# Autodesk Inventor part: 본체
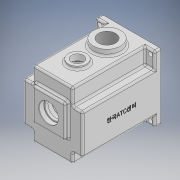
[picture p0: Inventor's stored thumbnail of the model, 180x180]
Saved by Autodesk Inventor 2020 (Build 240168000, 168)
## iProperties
Created: 2022-01
Part Number: 본체
Material: 일반
Document SubType Name: Modeling
Designer: user
Density: 1 g/cm^3
Appearance: 기본값
Mass: 521.293 g
Surface Area: 1157.23 cm^2
Volume: 521.293 cm^3
Author: user
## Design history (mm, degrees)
sketch "스케치1"
  geometry: L1 (49, -55)-(-49, -55); L2 (-49, -55)-(-49, 55); L3 (-49, 55)-(49, 55); L4 (49, 55)-(49, -55); L5 (49, -55)-(-49, 55); L6 (-49, -55)-(49, 55); 1 further point
  constraints: 12 end point, 2 midpoint, 2 parallel, 1 horizontal, 1 perpendicular
  dimensions: "d0" = 98 distance of L2.end L3.end; "d1" = 110 distance of L1.end L2.end
extrude "돌출1" new body sketch "스케치1" distance "d2" = 130; taper "d3" = 0 deg
sketch "스케치2"
  geometry: L1 (-49, 55)-(-49, -55) reference; L2 (-49, -55)-(-33, -55); L3 (-33, -55)-(-33, -38); L4 (-33, -38)-(-49, -38); L5 (-49, -38)-(-49, -55); L6 (49, 55)-(-49, 55) reference; L7 (-49, 55)-(-33, 55); L8 (-33, 55)-(-33, 28); L9 (-33, 28)-(-49, 28); L10 (-49, 28)-(-49, 55); L11 (0, 55)-(0, -55); L12 (-49, -55)-(49, -55) reference; L13 (49, 55)-(33, 55); L14 (33, 55)-(33, 28); L15 (33, 28)-(49, 28); L16 (49, 28)-(49, 55); L17 (49, -55)-(33, -55); L18 (33, -55)-(33, -38); L19 (33, -38)-(49, -38); L20 (49, -38)-(49, -55); 5 further points
  constraints: 34 end point, 6 symmetric about line, 4 parallel, 2 horizontal, 2 midpoint, 2 perpendicular
  dimensions: "d4" = 16 distance of L3.end L4.end; "d5" = 17 distance of L2.end L3.end; "d6" = 16 distance of L8.end L9.end; "d7" = 27 distance of L7.end L8.end
extrude "돌출2" cut sketch "스케치2" distance "d8" = 120; taper "d9" = 0 deg
sketch "스케치3"
  geometry: L1 (49, 0)-(49, -130); L2 (82, -130)-(16, -130) reference; L3 (98, 0)-(0, 0) reference; C1 r 15 at (49, -89); C2 r 22.5 at (49, -40)
  constraints: 2 centre point, 2 end point, 2 point on line, 1 midpoint
  dimensions: "d10" = 30 diameter of C1; "d11" = 45 diameter of C2; "d12" = 40 distance from line of L3 C2.centre; "d13" = 49 distance of C1.centre C2.centre
extrude "돌출3" join sketch "스케치3" distance "d14" = 10; taper "d15" = 0 deg
sketch "스케치4"
  geometry: L1 (22.5, 65)-(-22.5, 65) reference; L2 (0, 65)-(0, -55); L3 (33, -55)-(-33, -55) reference; L4 (49, -55)-(-49, -55) reference; L5 (23, -1)-(-23, -1); L6 (-23, -1)-(-23, 30.143); L7 (-23, 45)-(23, 45); L8 (23, 45)-(23, 30.143); L9 (23, -1)-(-23, 45); L10 (-23, -1)-(23, 45); L11 (-23, 30.143)-(-23, 45); L12 (23, 30.143)-(23, -1); A1 r 42 centre (0, -5) between (23, 30.143) and (-23, 30.143); A2 r 42 centre (0, -5) between (0, -47) and (23, 30.143); A3 r 42 centre (0, -5) between (-23, 30.143) and (0, -47); 2 further points
  constraints: 18 end point, 6 point on circle, 5 parallel, 4 midpoint, 3 centre point, 3 point on line, 2 perpendicular, 1 horizontal
  dimensions: "d35" = 84 diameter of A1; "d36" = 50 distance from line of L4 A1.centre; "d37" = 46 distance of L7.start L7.end; "d38" = 46 distance of L5.end L7.start; "d39" = 50 distance from line of A1.centre L7
extrude "돌출4" cut sketch "스케치4" distance "d20" = 121; taper "d21" = 0 deg
sketch "스케치7"
  geometry: L1 (33, 55)-(-33, 55) reference; L2 (0, 55)-(0, -55); L3 (-33, -55)-(33, -55) reference; L4 (27, -21)-(-27, -21); L5 (-27, -21)-(-27, 33); L6 (-27, 33)-(27, 33); L7 (27, 33)-(27, -21); L8 (27, -21)-(-27, 33); L9 (-27, -21)-(27, 33); A1 r 42 centre (0, -5) between (-23, 30.143) and (23, 30.143) reference; 2 further points
  constraints: 14 end point, 4 midpoint, 2 parallel, 1 horizontal, 1 perpendicular, 1 point on line
  dimensions: "d40" = 54 distance of L5.end L6.end; "d41" = 54 distance of L4.end L5.end; "d42" = 11 distance of point (0, 6) A1.centre
extrude "돌출7" join sketch "스케치7" distance "d43" = 7; taper "d44" = 0 deg
fillet "모깎기3" dims "d45" = 6
fillet "모깎기4" dims "d46" = 3
sketch "스케치8"
  geometry: L1 (23, 42)-(23, 33.249) reference; L2 (-20, 45)-(20, 45) reference; L3 (-23, 33.249)-(-23, 42) reference; L4 (-26, 33.249)-(-26, 42); L5 (-20, 48)-(20, 48); L6 (26, 42)-(26, 33.249); A1 r 42 centre (0, -5) between (-25.375, 28.468) and (25.375, 28.468) reference; A2 r 6 centre (29, 33.249) between (23, 33.249) and (25.375, 28.468) reference; A3 r 3 centre (20, 42) between (23, 42) and (20, 45) reference; A4 r 3 centre (-20, 42) between (-20, 45) and (-23, 42) reference; A5 r 6 centre (-29, 33.249) between (-25.375, 28.468) and (-23, 33.249) reference; A6 r 45 centre (0, -5) between (-27.188, 30.859) and (27.187, 30.859); A7 r 3 centre (-29, 33.249) between (-27.188, 30.859) and (-26, 33.249); A8 r 6 centre (-20, 42) between (-20, 48) and (-26, 42); A9 r 6 centre (20, 42) between (26, 42) and (20, 48); A10 r 3 centre (29, 33.249) between (26, 33.249) and (27.187, 30.859); 1 further point
  constraints: 10 point on circle, 6 end point, 5 centre point, 7 other
  dimensions: "d47" = 3 radial gap between concentric circles of A1 A6
extrude "돌출8" cut sketch "스케치8" distance "d48" = 9; taper "d49" = 0 deg
chamfer "모따기2" distance "d50" = 1; stored, may be unused: second distance "d51" = 2, angle "d52" = 45 deg
sketch "스케치9"
  geometry: C1 r 15 at (20, -32) reference; C2 r 22.5 at (20, -81) reference; C3 r 15 at (20, -32); 1 further point
  constraints: 1 centre point, 1 coincident
  dimensions: "d53" = 30 diameter of C3
extrude "돌출9" cut sketch "스케치9" distance "d54" = 5; taper "d55" = 0 deg
sketch "스케치10"
  geometry: C1 r 15 at (0, 0) reference; 2 further points
  constraints: 1 coincident
hole "구멍1" sketch "스케치10" at (0, 0) diameter "d56" = 20; stored, may be unused: countersink angle "d60" = 90 deg, drill point angle "d62" = 0 deg; dims "d57" = 4, "d58" = 4, "d59" = 2, "d61" = 6
chamfer "모따기3" distance "d63" = 1; stored, may be unused: second distance "d64" = 2, angle "d65" = 45 deg
sketch "스케치11"
  geometry: C1 r 22.5 at (0, 0) reference; 2 further points
  constraints: 1 coincident
hole "구멍2" sketch "스케치11" at (0, 0) diameter "d66" = 28.376; stored, may be unused: countersink angle "d70" = 90 deg, drill point angle "d72" = 0 deg; dims "d67" = 60, "d68" = 4, "d69" = 2, "d71" = 67.3
sketch "스케치12"
  geometry: L1 (27, 33)-(-27, 33) reference; L2 (27, -21)-(27, 33) reference; L3 (-27, 33)-(27, 33) reference; L4 (0, 33)-(0, -21); L5 (-27, 33)-(-27, -21) reference; L6 (-27, -21)-(27, -21) reference; L7 (-27, -21)-(-27, 33) reference; L8 (-27, 6)-(27, 6); L9 (27, 33)-(27, -21) reference; C1 r 16 at (0, 6); A1 r 42 centre (0, -5) between (-25.375, 28.468) and (25.375, 28.468) reference; 1 further point
  constraints: 4 end point, 4 midpoint, 1 centre point, 1 vertical
  dimensions: "d73" = 32 diameter of C1
extrude "돌출10" cut sketch "스케치12" distance "d74" = 8.3; taper "d75" = 0 deg
sketch "스케치13"
  geometry: C1 r 16 at (0, 6) reference; C2 r 21 at (0, 6); 1 further point
  constraints: 1 centre point, 1 coincident
  dimensions: "d76" = 42 diameter of C2
extrude "돌출11" join sketch "스케치13" distance "d77" = 7; taper "d78" = 0 deg
sketch "스케치14"
  geometry: C1 r 21 at (0, 0) reference; C2 r 17.5 at (0, 0); 1 further point
  constraints: 1 centre point, 1 coincident
  dimensions: "d79" = 35 diameter of C2
extrude "돌출12" cut sketch "스케치14" distance "d80" = 10; taper "d81" = 0 deg
sketch "스케치15"
  geometry: C1 r 16 at (0, 0) reference; C2 r 14 at (0, 0); 1 further point
  constraints: 1 centre point, 1 coincident
  dimensions: "d82" = 28 diameter of C2
extrude "돌출13" cut sketch "스케치15" stored distance "d83" = 10; taper "d84" = 0 deg
sketch "스케치16"
  geometry: L1 (33, -55)-(-33, -55) reference; L2 (0, -55)-(0, 55); L3 (-33, 55)-(33, 55) reference; C1 r 15 at (0, -25); 1 further point
  constraints: 2 end point, 2 midpoint, 1 centre point, 1 point on line
  dimensions: "d85" = 30 diameter of C1; "d86" = 30 distance from line of L1 C1.centre
extrude "돌출14" join sketch "스케치16" distance "d87" = 7; taper "d88" = 0 deg
sketch "스케치17"
  geometry: C1 r 11 at (0, -25); A1 r 15 centre (0, -25) between (-8.978, -12.984) and (8.978, -12.984) reference; 1 further point
  constraints: 1 centre point, 1 coincident
  dimensions: "d89" = 22 diameter of C1
extrude "돌출15" cut sketch "스케치17" distance "d90" = 7; taper "d91" = 0 deg
sketch "스케치18"
  geometry: C1 r 11 at (0, 0) reference; C2 r 9.5 at (0, 0); 1 further point
  constraints: 1 centre point, 1 coincident
  dimensions: "d92" = 19 diameter of C2
extrude "돌출16" cut sketch "스케치18" distance "d93" = 3; taper "d94" = 0 deg
fillet "모깎기5" dims "d95" = 3
fillet "모깎기6" dims "d96" = 0.3
chamfer "모따기4" distance "d97" = 1; stored, may be unused: second distance "d98" = 2, angle "d99" = 45 deg
chamfer "모따기5" distance "d100" = 0.8; stored, may be unused: second distance "d101" = 2, angle "d102" = 30 deg
fillet "모깎기7" dims "d103" = 0.3
fillet "모깎기8" dims "d104" = 3
fillet "모깎기9" dims "d105" = 3
fillet "모깎기10" dims "d106" = 3
sketch "스케치19"
  geometry: L1 (0, -5)-(-36, -5); L2 (0, -5)-(36, -5); L3 (-36, -5)-(-36, -1); L4 (-36, -1)-(-41.809, -1); L5 (-36, -1)-(-36, -9); L6 (-36, -9)-(-41.809, -9); L7 (36, -1)-(36, -9); L8 (36, -1)-(41.809, -1); L9 (36, -9)-(41.809, -9); A1 r 42 centre (0, -5) between (-25.375, 28.468) and (25.375, 28.468) reference; A2 r 36 centre (0, -5) between (-36, -5) and (36, -5); A3 r 4 centre (-36, -5) between (-36, -9) and (-36, -1); A4 r 4 centre (36, -5) between (36, -1) and (36, -9); A5 r 42 centre (0, -5) between (-25.375, 28.468) and (25.375, 28.468) reference; A6 r 4 centre (36, -5) between (36, -9) and (36, -1); A7 r 4 centre (-36, -5) between (-36, -1) and (-36, -9); 4 further points
  constraints: 18 end point, 14 point on circle, 5 centre point, 5 horizontal, 3 coincident, 3 tangent, 2 vertical, 1 parallel
  dimensions: "d110" = 72 diameter of A2; "d111" = 8 diameter of A3; "d112" = 8 diameter of A4
extrude "돌출17" join sketch "스케치19" stored distance "d113" = 3; taper "d114" = 0 deg
fillet "모깎기11" dims "d115" = 3
sketch "스케치20"
  geometry: A1 r 4 centre (-36, -5) between (-36, -9) and (-36, -1) reference; A2 r 4 centre (36, -5) between (36, -1) and (36, -9) reference; 3 further points
  constraints: 2 coincident
hole "구멍3" sketch "스케치20" at (-36, -5), (36, -5) diameter "d116" = 3.242; stored, may be unused: countersink angle "d120" = 90 deg, drill point angle "d122" = 118 deg; dims "d117" = 7, "d118" = 4, "d119" = 2, "d121" = 9
fillet "모깎기12" dims "d123" = 3
fillet "모깎기13" dims "d124" = 3
fillet "모깎기14" dims "d125" = 3
fillet "모깎기15" dims "d126" = 3
fillet "모깎기16" dims "d127" = 3
fillet "모깎기17" dims "d128" = 3
sketch "스케치21"
  geometry: L1 (-130, 77)-(-130, 17) reference; L2 (-7, 107)-(-127, 107) reference; 2 further points
  constraints: 1 other
  dimensions: "d129" = 65 distance from line of L1 point (-65, 47); "d130" = 60 distance from line of L2 point (-65, 47)
feature "엠보싱1" sketch "스케치21" dims "d4" = 16, "d5" = 17, "d6" = 16, "d7" = 27, "d131" = 0.5, "d132" = 0
sketch "스케치22"
  geometry: L1 (-46, 55)-(46, 55) reference; L2 (-49, -52)-(-49, 52) reference; L3 (46, -55)-(-46, -55) reference; L4 (49, 52)-(49, -52) reference; L5 (0, 55)-(0, -55); L6 (30, -55)-(-30, -55) reference; 5 further points
  constraints: 2 end point, 2 midpoint, 2 symmetric about line
  dimensions: "d133" = 7 distance from line of point (-42, 48) L1; "d134" = 7 distance from line of L2 point (-42, 48); "d135" = 7 distance from line of point (-42, -48) L3; "d136" = 7 distance from line of point (-42, -48) L2
hole "구멍4" sketch "스케치22" at (-42, 48), (-42, -48), (42, 48), (42, -48) diameter "d137" = 7; stored, may be unused: countersink angle "d141" = 90 deg, drill point angle "d143" = 0 deg; dims "d138" = 7, "d139" = 4, "d140" = 2, "d142" = 10
fillet "모깎기18" dims "d144" = 3
sketch "스케치23"
  geometry: C1 r 15 at (0, 0) reference; C2 r 15 at (0, 0); 1 further point
  constraints: 1 centre point, 1 coincident
extrude "돌출18" cut sketch "스케치23" distance "d145" = 5; taper "d146" = 0 deg
sketch "스케치24"
  geometry: C1 r 17.5 at (0, 6); A1 r 17.5 centre (0, 6) between (4.864, -10.81) and (-4.864, -10.81) reference; 3 further points
  constraints: 1 centre point, 1 coincident
extrude "돌출19" cut sketch "스케치24" distance "d147" = 7; taper "d148" = 0 deg
chamfer "모따기7" distance "d149" = 1; stored, may be unused: second distance "d150" = 2, angle "d151" = 45 deg
node "솔리드1"
feature "A9D066F2-1C7D-4E18-AEED-F7BC21143FA4" dims "d137" = 7, "d138" = 7, "d139" = 4, "d140" = 2, "d141" = 90 deg, "d142" = 10, "d143" = 0
